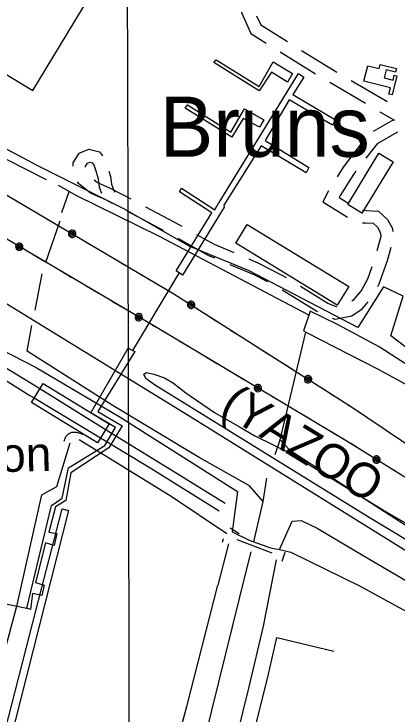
# Model space of a CAD drawing. Extents: x 3355677 to 3393573, y 612928 to 638357.
# Drawn here: x 3364774 to 3365699, y 627611 to 629298 of the extents above; entities that cross this region are included whole.
import ezdxf

# ---------------------------------------------------------------- set-up
doc = ezdxf.new("R2010")
doc.units = 0
for name, color, linetype in [('V-BLDG-OTLN', 7, 'Continuous'), ('V-GRID-MAJR', 7, 'Continuous'), ('V-RAIL-IDEN', 7, 'Continuous'), ('V-RAIL-TRAK', 7, 'Continuous'), ('V-ROAD-CNTR', 7, 'Continuous'), ('V-SITE-OTLN', 7, 'Continuous'), ('V-SITE-OTLN-IDEN', 7, 'Continuous'), ('V-SITE-VEGE', 7, 'Continuous'), ('V-TOPO-GNAM-IDEN', 7, 'Continuous'), ('V-TOPO-SHOR', 7, 'Continuous'), ('V-UTIL-LINE', 7, 'Continuous')]:
    doc.layers.add(name, color=color, linetype=linetype)

msp = doc.modelspace()

# ---------------------------------------------------------------- linework, layer by layer
at = {"layer": 'V-BLDG-OTLN'}
for points in [[(3365616.7, 629136.2), (3365625.9, 629173.8), (3365653.8, 629167), (3365656.2, 629176.6), (3365695.3, 629167), (3365693.3, 629158.5), (3365670.1, 629164.2), (3365665.3, 629144.3), (3365687, 629139), (3365689.9, 629151.2), (3365696.2, 629149.7), (3365684.9, 629103.4), (3365677.1, 629105.3), (3365680.8, 629120.5)], [(3365577.7, 628839.3), (3365653, 628963.2), (3365687.3, 628942.3), (3365612, 628818.4)], [(3365552.7, 628596.4), (3365308.2, 628746.2), (3365335.9, 628791.3), (3365580.4, 628641.5)], [(3364844, 628408.2), (3365002.8, 628310.4), (3364974.6, 628264.6), (3364815.8, 628362.3)]]:
    msp.add_lwpolyline(points, close=True, dxfattribs=at)
at = {"layer": 'V-GRID-MAJR'}
msp.add_spline([(3365072.5, 618325.9), (3365058.4, 624385.2), (3365044.3, 630446.4), (3365030.2, 636507.7), (3365030.2, 636509.6)], degree=3, dxfattribs=at)
at = {"layer": 'V-RAIL-TRAK'}
for points in [[(3365843.5, 627926.6), (3365193.4, 628330.6), (3364528.2, 628738.8), (3364216.4, 628928.8), (3364132.2, 628979.5)], [(3364836, 628395.2), (3364815, 628408.2), (3364612.7, 628531.1), (3364572.1, 628556.3), (3364535.5, 628581.8), (3364505.2, 628609.4), (3364476.9, 628643.7), (3364432.6, 628705.7), (3364402.6, 628758.2), (3364369.7, 628802.1), (3364347.8, 628826.8), (3364305.1, 628864.4), (3364216.4, 628928.8)], [(3364402.6, 628758.2), (3364452.4, 628666.5), (3364496, 628599.8), (3364532.2, 628563.4), (3364568.3, 628532), (3364669.6, 628468.3), (3364811.8, 628379.4), (3364822.4, 628373)], [(3365282.5, 628119), (3365143.3, 628204.7), (3365012.9, 628285.2), (3364836, 628395.2)], [(3364822.4, 628373), (3365099.2, 628206.1), (3365268.1, 628100.9)]]:
    msp.add_lwpolyline(points, dxfattribs=at)
at = {"layer": 'V-ROAD-CNTR'}
for p, q in [((3365415.4, 629207.2), (3365500.3, 629154.4)), ((3365534.6, 629133.9), (3365620.8, 629083.2)), ((3365134.3, 628776.3), (3365046, 628823.2)), ((3365505.3, 628580.9), (3365420, 628633.1)), ((3365315.9, 628046), (3365294.9, 628059)), ((3365290.6, 628021.7), (3365265, 627922.1)), ((3365276.1, 628025.4), (3365278.3, 628034.1)), ((3365420.2, 627979.8), (3365427.3, 628001.6))]:
    msp.add_line(p, q, dxfattribs=at)
for points in [[(3365321.9, 629302.9), (3365321.6, 629301.9), (3365344.7, 629251.2), (3365381.4, 629228.4)], [(3365358.2, 629294), (3365368.2, 629271.9), (3365432.6, 629231.9)], [(3365466.5, 629210.7), (3365524.2, 629174.8), (3365551.8, 629158.6)], [(3365586.3, 629138.3), (3365664.5, 629092.4), (3365672.6, 629087.8)], [(3365655.4, 629063), (3365690.8, 629042.9), (3365684.1, 629040.9), (3365638.9, 629015)], [(3365697.4, 629013.6), (3365696, 629013.2), (3365648.6, 628985.9), (3365621.8, 628951.2)], [(3365611.3, 628986.8), (3365566.8, 628929.2), (3365552.4, 628906.2)], [(3364916.1, 628931.6), (3364915.9, 628939.8), (3364930.8, 628963.3), (3364953.9, 628972.8), (3364979.6, 628966.1), (3364987.3, 628956.3)], [(3364946.2, 628929.4), (3364946.1, 628931.4), (3364951.1, 628939.2), (3364956.1, 628941.2), (3364962.2, 628939.6), (3364965.8, 628935.1), (3364971, 628920.8), (3364976.6, 628900.9), (3364979.1, 628881.3), (3364984.5, 628866.6)], [(3365002.5, 628919.7), (3365006, 628906.9), (3365008.5, 628888.5), (3365015.6, 628869)], [(3365597.3, 628919.6), (3365591.5, 628912), (3365559.3, 628860.8), (3365557.1, 628856.5), (3365578.3, 628843.2)], [(3365010.7, 628842), (3364995, 628850.3), (3364958.1, 628866.6), (3364929.3, 628890), (3364927, 628894.2)], [(3365055.7, 628852), (3365008.1, 628877.3), (3364973.9, 628892.4), (3364967.2, 628897.9)], [(3365531.4, 628872.1), (3365517.6, 628845.8), (3365577.2, 628808.5)], [(3365179.3, 628786.1), (3365173.1, 628789.6), (3365091.1, 628833.2)], [(3365613.3, 628825.5), (3365622, 628825.2), (3365652.3, 628823.3), (3365673.4, 628803), (3365684.8, 628782.7), (3365686.2, 628774.4)], [(3365613.6, 628795.5), (3365620.4, 628795.2), (3365639.5, 628794), (3365649.4, 628784.4), (3365656.1, 628772.5), (3365657.9, 628762.2), (3365648.2, 628727.4)], [(3365303.9, 628722.7), (3365256.6, 628742.7), (3365214.1, 628766.5)], [(3365257.4, 628709.8), (3365243.4, 628715.7), (3365169.5, 628757.2)], [(3365681.6, 628735.6), (3365672.7, 628703.6), (3365652.7, 628647.1), (3365649.5, 628641.1)], [(3365429.9, 628662.2), (3365418.2, 628669.4), (3365365.4, 628696.7), (3365340.7, 628707.2)], [(3365385.1, 628652.7), (3365352.6, 628669.6), (3365294.2, 628694.2)], [(3365635.8, 628689.4), (3365625.2, 628659.3), (3365610.2, 628631.3)], [(3365551.2, 628593.2), (3365550.5, 628593), (3365530, 628601), (3365464, 628641.3)], [(3365612, 628633.9), (3365589.9, 628608), (3365588, 628606.7)], [(3365626.5, 628604.7), (3365610.2, 628585.6), (3365588, 628570.2), (3365547.9, 628561.8), (3365541.5, 628564.3)], [(3364894.5, 628269.2), (3364899, 628280.3), (3364905.2, 628286.6), (3364912.7, 628290.7), (3364923.7, 628290.7), (3364932.6, 628288.6), (3364938.7, 628286.1)], [(3364721.6, 627655.6), (3364781.1, 627874.7), (3364840.5, 628139.3), (3364877, 628159.6), (3364908.8, 628264.8)], [(3364930.8, 628273.3), (3365152.3, 628136.4), (3365286.6, 628046.6)], [(3365413.6, 628007.8), (3365424.1, 628030.9), (3365443.6, 628076.1), (3365465.8, 628078.1), (3365504.1, 628059.4), (3365615.1, 627993.6), (3365797.7, 627886.5), (3365839, 627854.8), (3365823.1, 627741.6), (3365759, 627479.8), (3365705.6, 627265.5), (3365656.9, 627059.9), (3365561.6, 626679.7), (3365525.3, 626552.8)], [(3365310.6, 628032), (3365395.3, 627999.9)], [(3365405.4, 627982.7), (3365374.1, 627822.8), (3365339.5, 627677.2), (3365294.6, 627494.3), (3365242.6, 627275.9)], [(3365108.9, 627309), (3365125.3, 627390.3), (3365189.9, 627629.9), (3365265, 627922.1)]]:
    msp.add_lwpolyline(points, dxfattribs=at)
at = {"layer": 'V-SITE-OTLN'}
for points in [[(3364520.4, 629294.7), (3364819.5, 629113.7), (3365037.7, 629475.2)], [(3366102.4, 629299.9), (3366013, 628862.9), (3365924.7, 628460.4), (3365892.5, 628440.8), (3365836.3, 628432.9), (3365756.1, 628465.5), (3365681.4, 628522.5), (3365711.5, 628618.4), (3365663.9, 628640.5), (3365602.5, 628542.5), (3365338.5, 628679.9), (3365195.8, 628738.5), (3365041.2, 628827), (3364831.4, 628932.6), (3364728.8, 628986.2)], [(3364649.5, 628537.3), (3364827.1, 628446.2), (3365027.5, 628328.8), (3365312.1, 628147.7), (3365299.3, 628050.2), (3365340.5, 628030.5), (3365392.1, 628011.9), (3365413.5, 628007.6), (3365441, 628001.3), (3365607.5, 627919.9), (3365831, 627797.8), (3365865.7, 627775.3), (3365711.4, 627172.4)]]:
    msp.add_lwpolyline(points, dxfattribs=at)
at = {"layer": 'V-SITE-VEGE'}
msp.add_lwpolyline([(3366489.6, 627548.7), (3366190.1, 627747), (3365625.5, 628087.7), (3365112.6, 628404.6), (3365091.1, 628419.7), (3365086.8, 628430.5), (3365093.2, 628434.8), (3365110.5, 628430.5), (3365136.3, 628421.9), (3365157.9, 628408.9), (3365188, 628385.2), (3365257, 628337.8), (3365317.3, 628303.3), (3365354, 628281.7), (3365442.3, 628238.6), (3365670.7, 628098.5), (3365987.5, 627915.2), (3366364.6, 627667.3), (3366894.7, 627350.3)], dxfattribs=at)
at = {"layer": 'V-TOPO-SHOR'}
for p, q in [((3364888.9, 628820.1), (3364906.9, 628870.5)), ((3364850.1, 628700.5), (3364885.1, 628799.7)), ((3364824.7, 628584.7), (3364841.6, 628672.2))]:
    msp.add_line(p, q, dxfattribs=at)
for points in [[(3364851.8, 628898.8), (3364664.5, 628993.9), (3364493.1, 629086.1), (3364466.8, 629099.8), (3364453.2, 629095.3), (3364444.7, 629080.1)], [(3365483.9, 628572.7), (3365124.1, 628762.2), (3364923.8, 628861.1), (3364906.9, 628870.5), (3364881.3, 628884.9)], [(3365814.7, 628391.7), (3365653.3, 628495.9), (3365552.9, 628550.3), (3365487.1, 628582.3), (3365483.9, 628572.7), (3365470.9, 628534.6), (3365477.1, 628531.5), (3365651.5, 628442.8), (3365849.2, 628334.2)], [(3364805.4, 628485.6), (3364812.2, 628521), (3364817, 628548)], [(3365402.8, 628236.8), (3365415, 628272.5), (3365477.1, 628531.5)], [(3365373.9, 628123.4), (3365341.5, 628161.4), (3365219.7, 628229.4), (3365010.1, 628356.1), (3364805.4, 628485.6)], [(3365415, 628272.5), (3365437.5, 628248.2), (3365596.4, 628144.1), (3365786.1, 628022.4), (3366022.3, 627879.6), (3366304.6, 627709.8), (3366298.7, 627665.3)], [(3365351.2, 628026.7), (3365373.9, 628123.4), (3365382.8, 628179.8)], [(3365165.4, 627293.7), (3365233.4, 627551.4), (3365333.8, 627958), (3365345.1, 628001.9)]]:
    msp.add_lwpolyline(points, dxfattribs=at)
at = {"layer": 'V-UTIL-LINE'}
for p, q in [((3365255, 629181.7), (3365260.8, 629188)), ((3365186.5, 629071.1), (3365191.6, 629079.6)), ((3365548.3, 629043.6), (3365541.5, 629030.5)), ((3365048.6, 628492.9), (3365065, 628485)), ((3364484.9, 627932.5), (3364804.9, 627866.6))]:
    msp.add_line(p, q, dxfattribs=at)
for points in [[(3370599.1, 625159.7), (3369954, 625561.1), (3369433, 625883.7), (3369003.6, 626135.6), (3368625.6, 626361.6), (3368231.9, 626619.3), (3367851.3, 626850.7), (3367382.4, 627145.7), (3366865, 627444.4), (3366480, 627712.3), (3366027.6, 627988.3), (3365574.4, 628269.8), (3365118.6, 628541.7), (3364545.7, 628879.7), (3364115.5, 629158.1), (3363633, 629456.1), (3363159.7, 629754.2), (3362684.9, 630044.1), (3362215.7, 630326.1), (3361710.6, 630626.7), (3361234.6, 630908.5), (3360733.5, 631217), (3359805.2, 631780.2)], [(3360754.9, 631203.8), (3361272.8, 630966.2), (3361739.5, 630687.3), (3362229.5, 630409.9), (3362725.1, 630088.2), (3363192.5, 629799.9), (3363660, 629518.9), (3364148.1, 629221.1), (3365159.2, 628623.7), (3365586.8, 628351.6), (3366029.2, 628054), (3366448.3, 627803.7), (3366902.5, 627514.5), (3367411.9, 627203.2), (3367902.7, 626885.8), (3368361.7, 626578.4)], [(3365260.8, 629188), (3365364.3, 629123.9), (3365397.9, 629183.4), (3365444.7, 629155), (3365433, 629134.4), (3365394, 629158.5), (3365364.1, 629113.2), (3365255, 629181.7)], [(3365541.5, 629030.5), (3365436.5, 629091.3), (3365379, 628993.9), (3365484, 628928.7), (3365477.3, 628915.6), (3365369, 628980.8), (3365279, 628837.6), (3365280.1, 628833.1), (3365179.9, 628669.1), (3365164.6, 628679.2), (3365250.1, 628819.2), (3365172.5, 628869.8), (3365177, 628878.5), (3365257.9, 628826.8), (3365267, 628844.3), (3365268.1, 628844.3), (3365459.3, 629154.9), (3365472.4, 629145.9), (3365445.4, 629104.4), (3365548.3, 629043.6)], [(3365191.6, 629079.6), (3365295.8, 629013.3), (3365329.3, 629070), (3365375.4, 629043.7), (3365365.2, 629026), (3365325.5, 629046.5), (3365298.5, 629001.8), (3365186.5, 629071.1)], [(3364787.1, 628843.5), (3364816.4, 628826.2)], [(3364850.8, 628805.9), (3364880.1, 628788.6)], [(3364913.7, 628768.8), (3364913.4, 628771.6), (3364911.6, 628770.2), (3364911.9, 628767.4), (3364914.6, 628766.2), (3364916.4, 628769.1), (3364915.4, 628773.6), (3364911.1, 628774.1), (3364907.6, 628770.7), (3364908.6, 628766.2), (3364911.8, 628763.2), (3364916.6, 628763.9), (3364919.7, 628768.5), (3364918.2, 628776.5), (3364914.9, 628777.7), (3364911.4, 628777.5), (3364908.2, 628776), (3364905.9, 628773.3), (3364904.7, 628770), (3364904.9, 628766.5), (3364906.5, 628763.4), (3364909.1, 628761), (3364912.4, 628759.8), (3364915.9, 628760), (3364919.1, 628761.6), (3364921.4, 628764.2), (3364922.6, 628767.5), (3364922.4, 628771), (3364920.8, 628774.2), (3364918.2, 628776.5)], [(3364786.5, 628737.6), (3364786.7, 628734.7), (3364788.5, 628736.2), (3364788.3, 628738.9), (3364785.6, 628740.1), (3364783.7, 628737.3), (3364784.8, 628732.7), (3364789.1, 628732.3), (3364792.5, 628735.7), (3364791.6, 628740.1), (3364788.4, 628743.2), (3364783.6, 628742.4), (3364780.5, 628737.9), (3364782, 628729.8), (3364785.3, 628728.7), (3364788.8, 628728.9), (3364791.9, 628730.4), (3364794.3, 628733), (3364795.4, 628736.3), (3364795.3, 628739.8), (3364793.7, 628743), (3364791.1, 628745.4), (3364787.8, 628746.5), (3364784.3, 628746.3), (3364781.1, 628744.8), (3364778.8, 628742.2), (3364777.6, 628738.9), (3364777.8, 628735.4), (3364779.3, 628732.2), (3364782, 628729.8)], [(3364947.2, 628748.9), (3364976.5, 628731.6)], [(3364849.4, 628700.5), (3364820.1, 628717.8)], [(3365010.9, 628711.3), (3365040.2, 628694)], [(3364913.1, 628662.9), (3364883.9, 628680.2)], [(3365172, 628674.3), (3365166.4, 628665.6), (3365059.2, 628487.8)], [(3365074.6, 628673.6), (3365103.9, 628656.3)], [(3364976.9, 628625.3), (3364947.6, 628642.6)], [(3365138.4, 628636), (3365159.2, 628623.7), (3365167.5, 628618.4)], [(3365040.6, 628587.7), (3365011.3, 628605)], [(3365200.4, 628597.5), (3365200.2, 628600.3), (3365198.4, 628598.9), (3365198.6, 628596.2), (3365201.2, 628594.9), (3365203.2, 628597.7), (3365202.3, 628602.3), (3365198, 628602.9), (3365194.4, 628599.6), (3365195.2, 628595.1), (3365198.3, 628591.9), (3365203.1, 628592.5), (3365206.4, 628597), (3365205.2, 628605.1), (3365201.9, 628606.3), (3365198.4, 628606.3), (3365195.2, 628604.8), (3365192.8, 628602.3), (3365191.5, 628599), (3365191.6, 628595.5), (3365193, 628592.3), (3365195.5, 628589.9), (3365198.8, 628588.6), (3365202.3, 628588.7), (3365205.5, 628590.1), (3365208, 628592.6), (3365209.2, 628595.9), (3365209.1, 628599.4), (3365207.7, 628602.6), (3365205.2, 628605.1)], [(3365074.2, 628567.9), (3365074.4, 628565), (3365076.2, 628566.5), (3365076, 628569.2), (3365073.3, 628570.4), (3365071.4, 628567.6), (3365072.5, 628563), (3365076.7, 628562.6), (3365080.2, 628566), (3365079.3, 628570.5), (3365076, 628573.5), (3365071.3, 628572.7), (3365068.2, 628568.2), (3365069.6, 628560.2), (3365073, 628559), (3365076.5, 628559.2), (3365079.6, 628560.7), (3365082, 628563.3), (3365083.1, 628566.6), (3365082.9, 628570.2), (3365081.4, 628573.3), (3365078.8, 628575.7), (3365075.5, 628576.8), (3365072, 628576.6), (3365068.8, 628575.1), (3365066.5, 628572.5), (3365065.3, 628569.2), (3365065.5, 628565.7), (3365067, 628562.5), (3365069.6, 628560.2)], [(3365233.3, 628576.5), (3365262, 628558.3)], [(3365137, 628530.7), (3365118.6, 628541.7), (3365107.8, 628548.1)], [(3365295.7, 628536.8), (3365324.4, 628518.6)], [(3365200.6, 628492.8), (3365171.4, 628510.2)], [(3365358.1, 628497.1), (3365386.8, 628478.9)], [(3365065, 628485), (3364976.1, 628340.6), (3365034.1, 628305.7), (3365002.6, 628253.2), (3364910.4, 628192.6), (3364898.5, 628125.6), (3364874.1, 628110.4), (3364857.9, 628050), (3364876.6, 628046.5), (3364870.7, 628017.9), (3364849.9, 628023.7), (3364825.5, 627928.1), (3364846.4, 627922.3), (3364840.6, 627897.1), (3364818.6, 627901.7), (3364813.7, 627863.2), (3364804.9, 627866.6), (3364864.2, 628113.9), (3364889.8, 628131.2), (3364905, 628204.8), (3364992.7, 628258.8), (3365018.6, 628301.5), (3364958.5, 628337.5), (3365048.6, 628492.9)], [(3365264.1, 628454.9), (3365234.9, 628472.3)], [(3365420.6, 628457.4), (3365449.3, 628439.1)], [(3365327.7, 628417), (3365298.5, 628434.4)], [(3365482.2, 628418.2), (3365482.1, 628421.1), (3365480.2, 628419.7), (3365480.4, 628416.9), (3365483, 628415.6), (3365485, 628418.4), (3365484.1, 628423), (3365479.8, 628423.6), (3365476.2, 628420.3), (3365477, 628415.8), (3365480.2, 628412.7), (3365484.9, 628413.3), (3365488.2, 628417.7), (3365487, 628425.8), (3365483.7, 628427.1), (3365480.2, 628427), (3365477, 628425.6), (3365474.6, 628423), (3365473.3, 628419.8), (3365473.4, 628416.2), (3365474.8, 628413), (3365477.3, 628410.6), (3365480.6, 628409.3), (3365484.1, 628409.4), (3365487.3, 628410.8), (3365489.8, 628413.4), (3365491, 628416.6), (3365491, 628420.2), (3365489.5, 628423.4), (3365487, 628425.8)], [(3365361.2, 628397), (3365361.4, 628394.1), (3365363.2, 628395.6), (3365362.9, 628398.3), (3365360.3, 628399.5), (3365358.4, 628396.7), (3365359.4, 628392.1), (3365363.7, 628391.7), (3365367.2, 628395), (3365366.3, 628399.5), (3365363, 628402.6), (3365358.3, 628401.9), (3365355.2, 628397.3), (3365356.6, 628389.3), (3365359.9, 628388.1), (3365363.4, 628388.3), (3365366.5, 628389.8), (3365368.9, 628392.4), (3365370.1, 628395.7), (3365369.9, 628399.2), (3365368.4, 628402.4), (3365365.8, 628404.7), (3365362.5, 628405.9), (3365359, 628405.7), (3365355.8, 628404.2), (3365353.4, 628401.6), (3365352.3, 628398.3), (3365352.4, 628394.8), (3365354, 628391.6), (3365356.6, 628389.3)], [(3365515.1, 628397.3), (3365543.8, 628379)], [(3365423.9, 628359.6), (3365394.7, 628377)], [(3365577.5, 628357.6), (3365586.8, 628351.6), (3365605.9, 628338.8)], [(3365487.4, 628321.7), (3365458.2, 628339.1)], [(3365639.1, 628316.5), (3365667.3, 628297.5)], [(3365550.9, 628283.8), (3365521.8, 628301.2)], [(3365614.1, 628245.1), (3365585.2, 628263.1)], [(3365647.2, 628224.6), (3365647.3, 628221.7), (3365649.2, 628223.1), (3365649, 628225.8), (3365646.3, 628227.1), (3365644.4, 628224.3), (3365645.4, 628219.7), (3365649.6, 628219.2), (3365653.2, 628222.5), (3365652.3, 628227), (3365649.2, 628230.1), (3365644.4, 628229.5), (3365641.2, 628225), (3365642.5, 628216.9), (3365645.7, 628215.7), (3365649.2, 628215.8), (3365652.4, 628217.2), (3365654.8, 628219.8), (3365656.1, 628223.1), (3365656, 628226.6), (3365654.5, 628229.8), (3365651.9, 628232.2), (3365648.7, 628233.4), (3365645.2, 628233.3), (3365642, 628231.9), (3365639.6, 628229.3), (3365638.3, 628226), (3365638.4, 628222.5), (3365639.9, 628219.3), (3365642.5, 628216.9)], [(3365709.2, 628186), (3365680.3, 628204)], [(3364736.4, 627512.4), (3364826.4, 627859.9), (3364889.5, 628106.2), (3364905.1, 628101.7), (3364762.4, 627537.8)], [(3365163.8, 626805.8), (3365198.7, 626941.9), (3365262.3, 627195.5), (3365323.9, 627454.8), (3365387, 627707.1), (3365407.2, 627795.9), (3365544.4, 627762.6)]]:
    msp.add_lwpolyline(points, dxfattribs=at)

# ---------------------------------------------------------------- texts
at = {"layer": 'V-RAIL-IDEN'}
msp.add_text('(YAZOO', height=83, rotation=328.6097, dxfattribs=at).set_placement((3365266.7, 628339.3))
at = {"layer": 'V-SITE-OTLN-IDEN'}
msp.add_text('Substation', height=83, rotation=1.3328, dxfattribs=at).set_placement((3364340.2, 628185.1))
at = {"layer": 'V-TOPO-GNAM-IDEN'}
msp.add_text('Bruns', height=145, rotation=359.9881, dxfattribs=at).set_placement((3365124.5, 628954.3))

doc.saveas('drawing.dxf')
